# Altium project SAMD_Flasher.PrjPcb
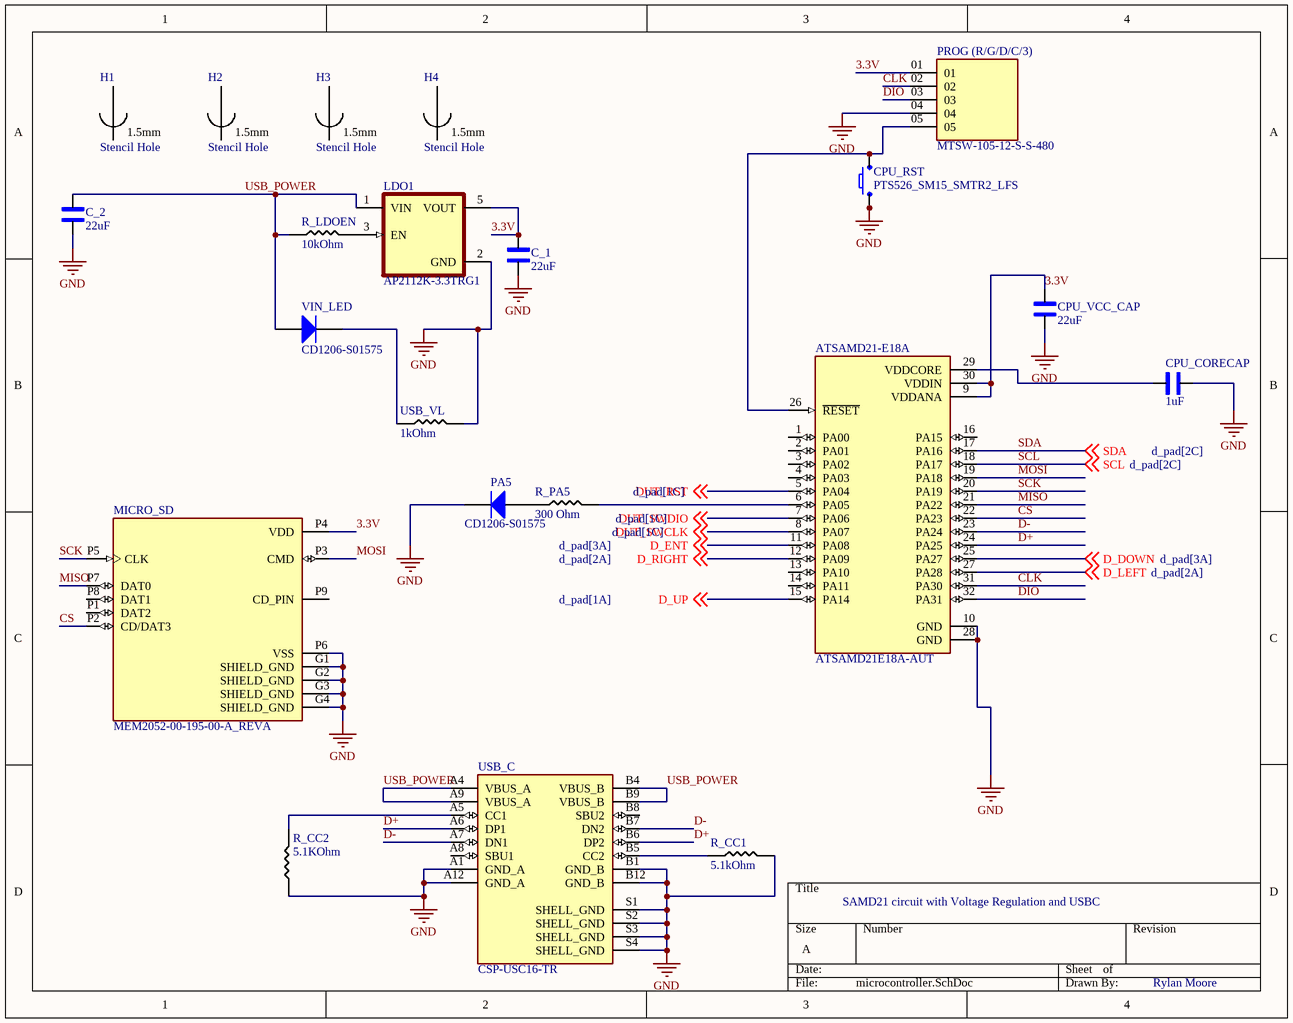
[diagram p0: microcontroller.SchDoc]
2 sheets, 36 parts. Net scope: global (net labels, ports and power ports of the same name join across sheets).
Board file: PCB1.PcbDoc
Sheets:
  microcontroller.SchDoc
  d_pad.SchDoc

## Sheet microcontroller.SchDoc
size A; SheetNumber: 1; SheetTotal: 2

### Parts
ATSAMD21-E18A  ATSAMD21E18A-AUT  [QFP80P900X900X120-32N]
C_1  22uF  [1206_Passive_Capacitor]
C_2  22uF  [1206_Passive_Capacitor]
CPU_CORECAP  value 1uF  [1206_Passive_Capacitor]  (hidden comment: 22uF)
CPU_RST  PTS526_SM15_SMTR2_LFS  [PTS526SM15SMTR2LFS]
CPU_VCC_CAP  22uF  [1206_Passive_Capacitor]
H1  Stencil Hole  [AlignmentHole_1.5mm]
H2  Stencil Hole  [AlignmentHole_1.5mm]
H3  Stencil Hole  [AlignmentHole_1.5mm]
H4  Stencil Hole  [AlignmentHole_1.5mm]
LDO1  AP2112K-3.3TRG1  [SOT95P285X140-5N]
MICRO_SD  MEM2052-00-195-00-A_REVA  [GCT_MEM2052-00-195-00-A_REVA]
PA5  CD1206-S01575  [BOUR-CD1206-S01575-2_L]
PROG_(R/G/D/C/3)  MTSW-105-12-S-S-480  [SAMTEC_MTSW-105-12-S-S-480]
R_CC1  value 5.1kOhm  [1206_Passive_Resitor]  (hidden comment: 100KOhm)
R_CC2  value 5.1KOhm  [1206_Passive_Resitor]  (hidden comment: 100KOhm)
R_LDOEN  value 10kOhm  [1206_Passive_Resitor]  (hidden comment: 1 Ohm)
R_PA5  value 300 Ohm  [1206_Passive_Resitor]  (hidden comment: 100Ohm)
USB_C  CSP-USC16-TR  [VALCON_CSP-USC16-TR]
USB_VL  value 1kOhm  [1206_Passive_Resitor]  (hidden comment: 100Ohm)
VIN_LED  CD1206-S01575  [BOUR-CD1206-S01575-2_L]

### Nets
GND: ATSAMD21-E18A.10(GND) ATSAMD21-E18A.28(GND) C_1.1 C_2.1 CPU_CORECAP.2 CPU_RST.1 CPU_RST.2 CPU_VCC_CAP.1 LDO1.2(GND) MICRO_SD.G1(SHIELD_GND) MICRO_SD.G2(SHIELD_GND) MICRO_SD.G3(SHIELD_GND) MICRO_SD.G4(SHIELD_GND) MICRO_SD.P6(VSS) PA5.2(K) PROG_(R/G/D/C/3).04 R_CC1.2 R_CC2.1 USB_C.A1(GND_A) USB_C.A12(GND_A) USB_C.B1(GND_B) USB_C.B12(GND_B) USB_C.S1(SHELL_GND) USB_C.S2(SHELL_GND) USB_C.S3(SHELL_GND) USB_C.S4(SHELL_GND) USB_VL.2
3.3V: ATSAMD21-E18A.9(VDDANA) ATSAMD21-E18A.30(VDDIN) C_1.2 CPU_VCC_CAP.2 LDO1.5(VOUT) MICRO_SD.P4(VDD) PROG_(R/G/D/C/3).01
CLK: ATSAMD21-E18A.31(PA30) PROG_(R/G/D/C/3).02
CS: ATSAMD21-E18A.22(PA23) MICRO_SD.P2(CD/DAT3)
D+: ATSAMD21-E18A.24(PA25) USB_C.A6(DP1) USB_C.B6(DP2)
D-: ATSAMD21-E18A.23(PA24) USB_C.A7(DN1) USB_C.B7(DN2)
D_DOWN: ATSAMD21-E18A.25(PA27) ; off-sheet D_DOWN
D_ENT: ATSAMD21-E18A.11(PA08) ; off-sheet D_ENT
D_LEFT: ATSAMD21-E18A.27(PA28) ; off-sheet D_LEFT
D_RIGHT: ATSAMD21-E18A.12(PA09) ; off-sheet D_RIGHT
D_UP: ATSAMD21-E18A.15(PA14) ; off-sheet D_UP
DIO: ATSAMD21-E18A.32(PA31) PROG_(R/G/D/C/3).03
DUT_RST: ATSAMD21-E18A.5(PA04) ; off-sheet DUT_RST
DUT_SWCLK: ATSAMD21-E18A.8(PA07) ; off-sheet DUT_SWCLK
DUT_SWDIO: ATSAMD21-E18A.7(PA06) ; off-sheet DUT_SWDIO
MISO: ATSAMD21-E18A.21(PA22) MICRO_SD.P7(DAT0)
MOSI: ATSAMD21-E18A.19(PA18) MICRO_SD.P3(CMD)
SCK: ATSAMD21-E18A.20(PA19) MICRO_SD.P5(CLK)
SCL: ATSAMD21-E18A.18(PA17) ; off-sheet SCL
SDA: ATSAMD21-E18A.17(PA16) ; off-sheet SDA
USB_POWER: C_2.2 LDO1.1(VIN) R_LDOEN.1 USB_C.A4(VBUS_A) USB_C.A9(VBUS_A) USB_C.B4(VBUS_B) USB_C.B9(VBUS_B) VIN_LED.1(A)
NetATSAMD21-E18A_6: ATSAMD21-E18A.6(PA05) R_PA5.2
NetATSAMD21-E18A_26: ATSAMD21-E18A.26(~{RESET}) CPU_RST.3 CPU_RST.4 PROG_(R/G/D/C/3).05
NetATSAMD21-E18A_29: ATSAMD21-E18A.29(VDDCORE) CPU_CORECAP.1
NetLDO1_3: LDO1.3(EN) R_LDOEN.2
NetPA5_1: PA5.1(A) R_PA5.1
NetR_CC1_1: R_CC1.1 USB_C.B5(CC2)
NetR_CC2_2: R_CC2.2 USB_C.A5(CC1)
NetUSB_VL_1: USB_VL.1 VIN_LED.2(K)

Not connected (* = marked no-connect by the designer): ATSAMD21-E18A 1(PA00) 2(PA01) 3(PA02) 4(PA03) 13(PA10) 14(PA11) 16(PA15); MICRO_SD P1(DAT2) P8(DAT1) P9(CD_PIN); USB_C A8(SBU1) B8(SBU2)

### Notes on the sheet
- SAMD21 circuit with Voltage Regulation and USBC
- Rylan Moore

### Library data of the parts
ATSAMD21-E18A = ATSAMD21E18A-AUT: ARM Cortex-M0+ SAM D21E Microcontroller IC 32-Bit 48MHz 256KB (256K x 8) FLASH 32-TQFP (7x7)
C_1 C_2 CPU_CORECAP CPU_VCC_CAP = C_22uF_1206: 22uF ±10% 25V X5R 1206 Multilayer Ceramic Capacitors MLCC - SMD/SMT RoHS; MFR Part #: CL31A226KAHNNNE
CPU_RST = CMP-005-000000-1: Tactile Switch SPST-NO Top Actuated Surface Mount; MP: PTS526 SM15 SMTR2 LFS; MF: C&K
H1-H4 = H_StencilAllignment_1.5mm: Stencil Allignment hole for use with 1.5mm pin
LDO1 = AP2112K-3.3TRG1: AP2112 Series 0.6 A 3.3 V Fixed Output SMT LDO Linear Regulator - SOT23-5; MF: {'manufacturer': u'Diodes Inc.'}
MICRO_SD = MEM2052-00-195-00-A_REVA: MF: {'manufacturer': u'Global Connector Technology'}
PA5 VIN_LED = CMP-0583-00001-2: 75 V Small Signal Switching Diode, 150 mA, 2.5 uA, 1026 Molded Package, RoHS, Tape and Reel; Manufacturer: Bourns; Reverse Voltage: 75 V; Average Forward Current: 150 mA; Reverse Current (Max.): 2.5 uA; Capacitance Between Terminals (Max.): 3 pF; Reverse Recovery Time (Max.): 4 nS; Forward Voltage (Max.): 1.00 V
PROG_(R/G/D/C/3) = MTSW-105-12-S-S-480: MF: {'manufacturer': u'Samtec'}
R_CC1 R_CC2 = R_100KOhm_1206: 100kΩ ±1% 0.25W ±100ppm/℃ 1206 Chip Resistor - Surface Mount RoHS; MFR Part #: 1206W4F1003T5E
R_LDOEN = R_1Ohm_1206: 1Ω ±5% 0.25W ±400ppm/℃ 1206 Chip Resistor - Surface Mount RoHS; MFR Part #: 1206W4J010JT5E
R_PA5 USB_VL = R_100Ohm_1206: 100Ω ±1% 0.25W ±100ppm/℃ 1206 Chip Resistor - Surface Mount RoHS; MFR Part #: 1206W4F1000T5E
USB_C = CSP-USC16-TR: MF: {'manufacturer': u'Valcon'}

## Sheet d_pad.SchDoc
size A; SheetNumber: 2; SheetTotal: 2
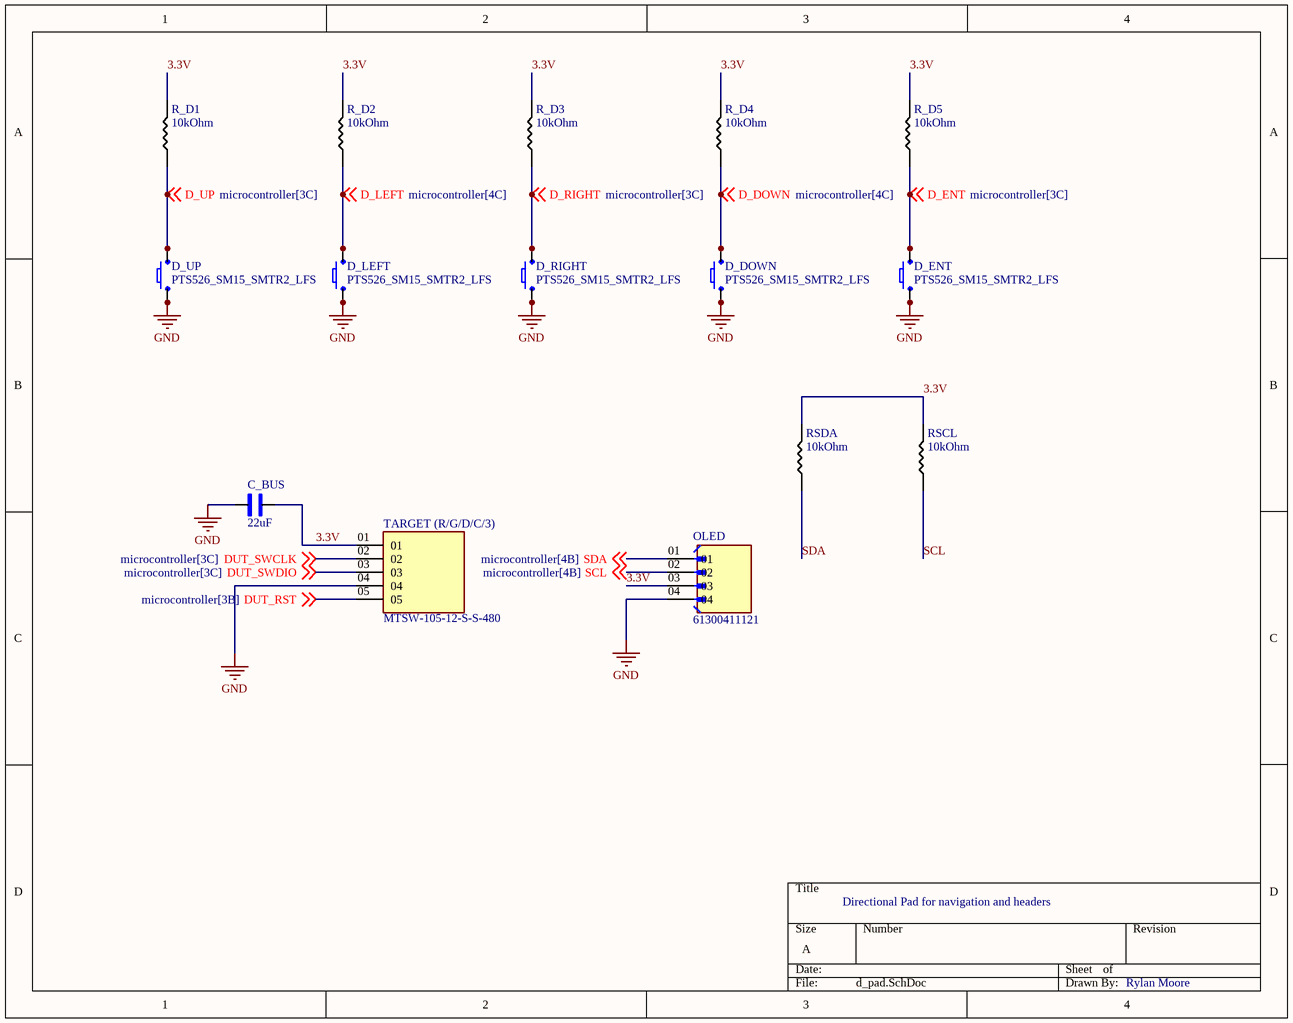
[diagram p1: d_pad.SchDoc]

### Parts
C_BUS  value 22uF  [1206_Passive_Capacitor]  (hidden comment: 10uF)
D_DOWN  PTS526_SM15_SMTR2_LFS  [PTS526SM15SMTR2LFS]
D_ENT  PTS526_SM15_SMTR2_LFS  [PTS526SM15SMTR2LFS]
D_LEFT  PTS526_SM15_SMTR2_LFS  [PTS526SM15SMTR2LFS]
D_RIGHT  PTS526_SM15_SMTR2_LFS  [PTS526SM15SMTR2LFS]
D_UP  PTS526_SM15_SMTR2_LFS  [PTS526SM15SMTR2LFS]
OLED  61300411121  [WURTH_61300411121]
R_D1  value 10kOhm  [1206_Passive_Resitor]  (hidden comment: 100Ohm)
R_D2  value 10kOhm  [1206_Passive_Resitor]  (hidden comment: 100Ohm)
R_D3  value 10kOhm  [1206_Passive_Resitor]  (hidden comment: 100Ohm)
R_D4  value 10kOhm  [1206_Passive_Resitor]  (hidden comment: 100Ohm)
R_D5  value 10kOhm  [1206_Passive_Resitor]  (hidden comment: 100Ohm)
RSCL  value 10kOhm  [1206_Passive_Resitor]  (hidden comment: 100Ohm)
RSDA  value 10kOhm  [1206_Passive_Resitor]  (hidden comment: 100Ohm)
TARGET_(R/G/D/C/3)  MTSW-105-12-S-S-480  [SAMTEC_MTSW-105-12-S-S-480]

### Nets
GND: C_BUS.1 D_DOWN.1 D_DOWN.2 D_ENT.1 D_ENT.2 D_LEFT.1 D_LEFT.2 D_RIGHT.1 D_RIGHT.2 D_UP.1 D_UP.2 OLED.04 TARGET_(R/G/D/C/3).04
3.3V: C_BUS.2 OLED.03 R_D1.2 R_D2.2 R_D3.2 R_D4.2 R_D5.2 RSCL.2 RSDA.2 TARGET_(R/G/D/C/3).01
D_DOWN: D_DOWN.3 D_DOWN.4 R_D4.1 ; off-sheet D_DOWN
D_ENT: D_ENT.3 D_ENT.4 R_D5.1 ; off-sheet D_ENT
D_LEFT: D_LEFT.3 D_LEFT.4 R_D2.1 ; off-sheet D_LEFT
D_RIGHT: D_RIGHT.3 D_RIGHT.4 R_D3.1 ; off-sheet D_RIGHT
D_UP: D_UP.3 D_UP.4 R_D1.1 ; off-sheet D_UP
DUT_RST: TARGET_(R/G/D/C/3).05 ; off-sheet DUT_RST
DUT_SWCLK: TARGET_(R/G/D/C/3).02 ; off-sheet DUT_SWCLK
DUT_SWDIO: TARGET_(R/G/D/C/3).03 ; off-sheet DUT_SWDIO
SCL: OLED.02 RSCL.1 ; off-sheet SCL
SDA: OLED.01 RSDA.1 ; off-sheet SDA

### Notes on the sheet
- Directional Pad for navigation and headers
- Rylan Moore

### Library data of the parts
C_BUS = C_10uF_1206: 10uF ±10% 50V X5R 1206 Multilayer Ceramic Capacitors MLCC - SMD/SMT RoHS; MFR Part #: CL31A106KBHNNNE
D_DOWN D_ENT D_LEFT D_RIGHT D_UP = CMP-005-000000-1: as CPU_RST on sheet microcontroller
OLED = 61300411121: <a href="https://pricing.snapeda.com/parts/61300411121/W%C3%BCrth%20Elektronik/view-part?ref=eda">Check availability</a>; MF: {'manufacturer': u'Wurth Electronics'}
R_D1-R_D5 RSCL RSDA = R_100Ohm_1206: as R_PA5 on sheet microcontroller
TARGET_(R/G/D/C/3) = MTSW-105-12-S-S-480: MF: {'manufacturer': u'Samtec'}

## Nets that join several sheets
GND: microcontroller (27 pins), d_pad (13 pins)
3.3V: microcontroller (7 pins), d_pad (10 pins)
D_DOWN: microcontroller (ATSAMD21-E18A.25), d_pad (D_DOWN.3 D_DOWN.4 R_D4.1)
D_ENT: microcontroller (ATSAMD21-E18A.11), d_pad (D_ENT.3 D_ENT.4 R_D5.1)
D_LEFT: microcontroller (ATSAMD21-E18A.27), d_pad (D_LEFT.3 D_LEFT.4 R_D2.1)
D_RIGHT: microcontroller (ATSAMD21-E18A.12), d_pad (D_RIGHT.3 D_RIGHT.4 R_D3.1)
D_UP: microcontroller (ATSAMD21-E18A.15), d_pad (D_UP.3 D_UP.4 R_D1.1)
DUT_RST: microcontroller (ATSAMD21-E18A.5), d_pad (TARGET_(R/G/D/C/3).05)
DUT_SWCLK: microcontroller (ATSAMD21-E18A.8), d_pad (TARGET_(R/G/D/C/3).02)
DUT_SWDIO: microcontroller (ATSAMD21-E18A.7), d_pad (TARGET_(R/G/D/C/3).03)
SCL: microcontroller (ATSAMD21-E18A.18), d_pad (OLED.02 RSCL.1)
SDA: microcontroller (ATSAMD21-E18A.17), d_pad (OLED.01 RSDA.1)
